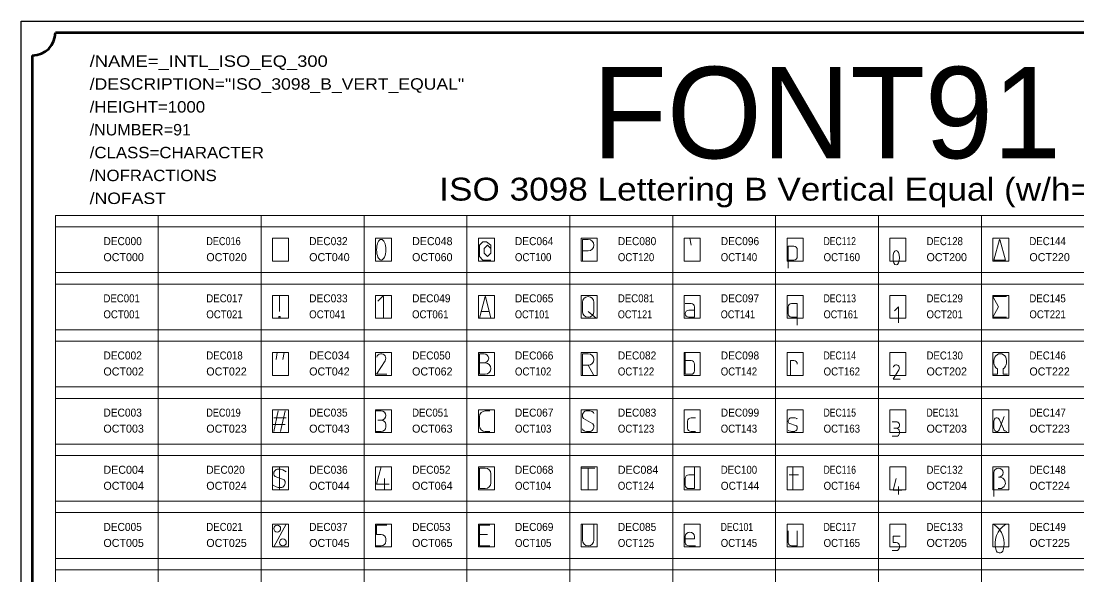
# Model space of a CAD drawing. Extents: x -200 to 7300, y -200 to 4800.
# Drawn here: x -200 to 4418, y 2378 to 4800 of the extents above; entities that cross this region are included whole.
import ezdxf
from ezdxf.enums import TextEntityAlignment as Align

# ---------------------------------------------------------------- set-up
doc = ezdxf.new("R2010")
doc.units = 0
doc.header["$LTSCALE"] = 14
for name, color, linetype, lineweight in [('1', 7, 'Continuous', 13), ('5', 7, 'Continuous', 40), ('6', 7, 'Continuous', 13), ('63', 7, 'Continuous', 13)]:
    doc.layers.add(name, color=color, linetype=linetype, lineweight=lineweight)
doc.layers.add('10', color=7, linetype='Continuous')
doc.layers.add('11', color=7, linetype='Continuous')

msp = doc.modelspace()

# ---------------------------------------------------------------- linework, layer by layer
at = {"layer": '1'}
for p, q in [((2730, 3820), (2725, 3850)), ((2280, 3795), (2255, 3795)), ((3195, 3800), (3195, 3770)), ((3180, 3755), (3155, 3755)), ((930, 3530), (930, 3600)), ((2255, 3570), (2255, 3530)), ((2305, 3570), (2305, 3530)), ((2705, 3565), (2730, 3565)), ((1813, 3530), (1848, 3530)), ((2315, 3500), (2280, 3530)), ((2720, 3535), (2745, 3535)), ((3155, 3550), (3155, 3520)), ((3170, 3505), (3195, 3505)), ((915, 3320), (920, 3350)), ((950, 3350), (945, 3320)), ((1830, 3305), (1805, 3305)), ((2280, 3295), (2255, 3295)), ((2305, 3250), (2280, 3295)), ((2730, 3315), (2705, 3315)), ((2745, 3270), (2745, 3300)), ((4055, 3315), (4055, 3305)), ((4110, 3315), (4110, 3305)), ((905, 3005), (925, 3095)), ((935, 3005), (955, 3095)), ((1375, 3095), (1350, 3095)), ((1850, 3095), (1830, 3095)), ((906, 3065), (960, 3065)), ((1375, 3055), (1360, 3055)), ((1805, 3070), (1805, 3030)), ((2715, 3050), (2715, 3020)), ((2750, 3065), (2730, 3065)), ((4055, 3050), (4055, 3020)), ((4097, 3016), (4078.8, 3055.9)), ((4100, 3070), (4079.6, 3016.6)), ((901, 3035), (955, 3035)), ((1375, 3005), (1350, 3005)), ((1395, 3035), (1395, 3025)), ((1830, 3005), (1850, 3005)), ((2730, 3005), (2750, 3005)), ((3158, 3041), (3192, 3029)), ((3628, 3047), (3610, 3047)), ((3628, 3019), (3617, 3019)), ((3642, 3005), (3642, 2998)), ((3628, 2984), (3610, 2984)), ((930, 2850), (930, 2750)), ((1855, 2820), (1855, 2780)), ((2250, 2845), (2310, 2845)), ((2280, 2845), (2280, 2750)), ((3175, 2850), (3175, 2750)), ((4055, 2720), (4055, 2825)), ((1390, 2750), (1390, 2800)), ((2705, 2770), (2705, 2800)), ((2720, 2815), (2745, 2815)), ((3160, 2815), (3200, 2815)), ((4075, 2805), (4080, 2805)), ((3638, 2730), (3638, 2765)), ((905, 2500), (960, 2600)), ((2255, 2600), (2255, 2530)), ((2305, 2600), (2305, 2530)), ((1840, 2555), (1805, 2555)), ((2705, 2520), (2705, 2545)), ((3155, 2570), (3155, 2520)), ((1350, 2505), (1375, 2505)), ((1395, 2535), (1395, 2525)), ((2750, 2505), (2720, 2505)), ((3642, 2505), (3642, 2498)), ((3610, 2484), (3628, 2484))]:
    msp.add_line(p, q, dxfattribs=at)
for points in [[(1855, 3755), (1820, 3755), (1805, 3770), (1805, 3820), (1820, 3835), (1835, 3835), (1855, 3820), (1855, 3785), (1840, 3770), (1825, 3785), (1825, 3805), (1840, 3820), (1855, 3805)], [(2280, 3845), (2255, 3845), (2255, 3750)], [(3155, 3720), (3155, 3815), (3180, 3815)], [(1385, 3500), (1385, 3595), (1380, 3595), (1360, 3575)], [(1805, 3500), (1829, 3595), (1831, 3595), (1855, 3500)], [(3195, 3470), (3195, 3565), (3170, 3565)], [(4110, 3595), (4050, 3595), (4075, 3550), (4050, 3505), (4110, 3505)], [(2745, 3550), (2745, 3505), (2720, 3505)], [(3638, 3480), (3638, 3550), (3620, 3533)], [(1825, 3345), (1805, 3345), (1805, 3255), (1830, 3255)], [(2280, 3345), (2255, 3345), (2255, 3250)], [(2705, 3350), (2705, 3255), (2730, 3255)], [(1400, 3255), (1355, 3255), (1391.8, 3314.1)], [(3180, 3315), (3165, 3315), (3165, 3250)], [(4050, 3255), (4070, 3255), (4070, 3279)], [(4115, 3255), (4095, 3255), (4095, 3279)], [(3645, 3234), (3614, 3234), (3639.3, 3274.9)], [(2305, 3083), (2303, 3088), (2298, 3092), (2294, 3094), (2287, 3095), (2270, 3095), (2266, 3094), (2262, 3091), (2258, 3085), (2256, 3081), (2255, 3077), (2255, 3069), (2260, 3062), (2300, 3038), (2305, 3031), (2305, 3023), (2304, 3019), (2302, 3015), (2298, 3009), (2294, 3006), (2290, 3005), (2273, 3005), (2266, 3006), (2262, 3008), (2257, 3012), (2255, 3017)], [(960, 2828), (945, 2837), (935, 2840), (920, 2840), (916, 2839), (912, 2836), (908.1, 2832), (905, 2827), (905, 2819), (906.8, 2812.7), (910.5, 2807.4), (950, 2793), (955, 2786), (955, 2778), (954, 2774), (952, 2770), (948, 2764), (944, 2761), (940, 2760), (925, 2760), (915, 2763), (900, 2772)], [(1410, 2775), (1355, 2775), (1375, 2850)], [(1830, 2845), (1805, 2845), (1805, 2755), (1830, 2755)], [(2745, 2850), (2745, 2755), (2720, 2755)], [(3652, 2748), (3614, 2748), (3628, 2800)], [(1400, 2595), (1355, 2595), (1355, 2555), (1375, 2555)], [(1850, 2595), (1805, 2595), (1805, 2505), (1850, 2505)], [(2705, 2535), (2745, 2535), (2745, 2545)], [(3170, 2505), (3195, 2505), (3195, 2570)], [(3645, 2547), (3614, 2547), (3614, 2519), (3628, 2519)]]:
    msp.add_lwpolyline(points, dxfattribs=at)
for points in [[(4055, 3755), (4105, 3755), (4081, 3845), (4079, 3845)], [(927, 3502), (933, 3502), (933, 3508), (927, 3508)]]:
    msp.add_lwpolyline(points, close=True, dxfattribs=at)
for centre in [(920, 2580), (945, 2520)]:
    msp.add_circle(centre, 15, dxfattribs=at)
for centre, radius, start, end in [((2280, 3820), 25, 270, 90), ((3180, 3800), 15, 0, 90), ((3180, 3770), 15, 270, 0), ((2280, 3570), 25, 0, 180), ((2730, 3550), 15, 0, 90), ((3170, 3550), 15, 90, 180), ((2280, 3530), 25, 180, 360), ((2720, 3520), 15, 90, 270), ((3170, 3520), 15, 180, 270), ((1375, 3325), 20, 327.0948, 165.9638), ((1825, 3325), 20, 270, 90), ((2280, 3320), 25, 270, 90), ((1830, 3280), 25, 270, 90), ((2730, 3300), 15, 0, 90), ((3180, 3300), 15, 0, 90), ((3627.5, 3282.5), 14, 327.0948, 165.9638), ((4085, 3305), 30, 180, 240), ((4080, 3305), 30, 300, 360), ((2730, 3270), 15, 270, 0), ((1375, 3075), 20, 270, 90), ((1830, 3070), 25, 90, 180), ((1375, 3035), 20, 0, 90), ((2730, 3050), 15, 90, 180), ((3170, 3050), 15, 105.9454, 216.8699), ((1375, 3025), 20, 270, 360), ((1830, 3030), 25, 180, 270), ((2730, 3020), 15, 180, 270), ((3180, 3020), 15, 287.9003, 36.8699), ((3628, 3033), 14, 265.8439, 90.0653), ((3628, 3005), 14, 0, 90), ((4111.2, 3020), 15, 196.6992, 270), ((3628, 2998), 14, 270, 360), ((1830, 2820), 25, 0, 90), ((4075, 2825), 20, 270, 180), ((1830, 2780), 25, 270, 0), ((2720, 2800), 15, 90, 180), ((4080, 2780), 25, 255.9638, 90), ((2720, 2770), 15, 180, 270), ((4000, 2515), 100, 340.6557, 58.2117), ((4160, 2515), 100, 121.7883, 197.354), ((1375, 2535), 20, 0, 90), ((2725, 2545), 20, 0, 180), ((1375, 2525), 20, 270, 0), ((2280, 2530), 25, 180, 360), ((2720, 2520), 15, 180, 270), ((3170, 2520), 15, 180, 270), ((3628, 2505), 14, 0, 90), ((3628, 2498), 14, 270, 360), ((4080.2, 2490.2), 16.4, 197.5688, 329.793)]:
    msp.add_arc(centre, radius, start, end, dxfattribs=at)
for centre, major_axis in [((1375, 3800), (0, -45)), ((3627.5, 3765), (0, -31.5))]:
    msp.add_ellipse(centre, major_axis=major_axis, ratio=0.444444, dxfattribs=at)
for centre, major_axis, ratio, start_param, end_param in [((4082.5, 3315), (0, 30), 0.916667, 4.712389, 7.853982), ((3175, 3060), (-20, 0), 0.25, 3.141593, 5.175477), ((4067.4, 3050), (0, 15), 0.826312, 5.117281, 7.853982), ((3175, 3010), (-20, 0), 0.25, 6.283185, 8.366111), ((4067.5, 3020), (0, 15), 0.831124, 1.570796, 4.483126)]:
    msp.add_ellipse(centre, major_axis=major_axis, ratio=ratio, start_param=start_param, end_param=end_param, dxfattribs=at)
at = {"layer": '5', "lineweight": 53}
for p, q in [((-50, 4750), (7150, 4750)), ((-150, -50), (-150, 4650))]:
    msp.add_line(p, q, dxfattribs=at)
at = {"layer": '5', "lineweight": 25}
msp.add_lwpolyline([(-200, -200), (-200, 4800), (7300, 4800), (7300, -200)], close=True, dxfattribs=at)
at = {"layer": '5', "lineweight": 53}
msp.add_arc((-150, 4750), 100, 270, 0, dxfattribs=at)
at = {"layer": '6'}
for p, q in [((-50, 3950), (7150, 3950)), ((-50, 3950), (-50, -50)), ((400, 3950), (400, -50)), ((850, 3950), (850, -50)), ((1300, 3950), (1300, -50)), ((1750, 3950), (1750, -50)), ((2200, 3950), (2200, -50)), ((2650, 3950), (2650, -50)), ((3100, 3950), (3100, -50)), ((3550, 3950), (3550, -50)), ((4000, 3950), (4000, -50)), ((-50, 3900), (7150, 3900)), ((-50, 3700), (7150, 3700)), ((-50, 3650), (7150, 3650)), ((-50, 3450), (7150, 3450)), ((-50, 3400), (7150, 3400)), ((-50, 3200), (7150, 3200)), ((-50, 3150), (7150, 3150)), ((-50, 2950), (7150, 2950)), ((-50, 2900), (7150, 2900)), ((-50, 2700), (7150, 2700)), ((-50, 2650), (7150, 2650)), ((-50, 2450), (7150, 2450)), ((-50, 2400), (7150, 2400))]:
    msp.add_line(p, q, dxfattribs=at)
at = {"layer": '63'}
for points in [[(900, 3750), (970, 3750), (970, 3850), (900, 3850)], [(1350, 3750), (1420, 3750), (1420, 3850), (1350, 3850)], [(1800, 3750), (1870, 3750), (1870, 3850), (1800, 3850)], [(2250, 3750), (2320, 3750), (2320, 3850), (2250, 3850)], [(2700, 3750), (2770, 3750), (2770, 3850), (2700, 3850)], [(3150, 3750), (3220, 3750), (3220, 3850), (3150, 3850)], [(3600, 3750), (3670, 3750), (3670, 3850), (3600, 3850)], [(4050, 3750), (4120, 3750), (4120, 3850), (4050, 3850)], [(900, 3500), (970, 3500), (970, 3600), (900, 3600)], [(1350, 3500), (1420, 3500), (1420, 3600), (1350, 3600)], [(1800, 3500), (1870, 3500), (1870, 3600), (1800, 3600)], [(2250, 3500), (2320, 3500), (2320, 3600), (2250, 3600)], [(2700, 3500), (2770, 3500), (2770, 3600), (2700, 3600)], [(3150, 3500), (3220, 3500), (3220, 3600), (3150, 3600)], [(3600, 3500), (3670, 3500), (3670, 3600), (3600, 3600)], [(4050, 3500), (4120, 3500), (4120, 3600), (4050, 3600)], [(900, 3250), (970, 3250), (970, 3350), (900, 3350)], [(1350, 3250), (1420, 3250), (1420, 3350), (1350, 3350)], [(1800, 3250), (1870, 3250), (1870, 3350), (1800, 3350)], [(2250, 3250), (2320, 3250), (2320, 3350), (2250, 3350)], [(2700, 3250), (2770, 3250), (2770, 3350), (2700, 3350)], [(3150, 3250), (3220, 3250), (3220, 3350), (3150, 3350)], [(3600, 3250), (3670, 3250), (3670, 3350), (3600, 3350)], [(4050, 3250), (4120, 3250), (4120, 3350), (4050, 3350)], [(900, 3000), (970, 3000), (970, 3100), (900, 3100)], [(1350, 3000), (1420, 3000), (1420, 3100), (1350, 3100)], [(1800, 3000), (1870, 3000), (1870, 3100), (1800, 3100)], [(2250, 3000), (2320, 3000), (2320, 3100), (2250, 3100)], [(2700, 3000), (2770, 3000), (2770, 3100), (2700, 3100)], [(3150, 3000), (3220, 3000), (3220, 3100), (3150, 3100)], [(3600, 3000), (3670, 3000), (3670, 3100), (3600, 3100)], [(4050, 3000), (4120, 3000), (4120, 3100), (4050, 3100)], [(900, 2750), (970, 2750), (970, 2850), (900, 2850)], [(1350, 2750), (1420, 2750), (1420, 2850), (1350, 2850)], [(1800, 2750), (1870, 2750), (1870, 2850), (1800, 2850)], [(2250, 2750), (2320, 2750), (2320, 2850), (2250, 2850)], [(2700, 2750), (2770, 2750), (2770, 2850), (2700, 2850)], [(3150, 2750), (3220, 2750), (3220, 2850), (3150, 2850)], [(3600, 2750), (3670, 2750), (3670, 2850), (3600, 2850)], [(4050, 2750), (4120, 2750), (4120, 2850), (4050, 2850)], [(900, 2500), (970, 2500), (970, 2600), (900, 2600)], [(1350, 2500), (1420, 2500), (1420, 2600), (1350, 2600)], [(1800, 2500), (1870, 2500), (1870, 2600), (1800, 2600)], [(2250, 2500), (2320, 2500), (2320, 2600), (2250, 2600)], [(2700, 2500), (2770, 2500), (2770, 2600), (2700, 2600)], [(3150, 2500), (3220, 2500), (3220, 2600), (3150, 2600)], [(3600, 2500), (3670, 2500), (3670, 2600), (3600, 2600)], [(4050, 2500), (4120, 2500), (4120, 2600), (4050, 2600)]]:
    msp.add_lwpolyline(points, close=True, dxfattribs=at)

# ---------------------------------------------------------------- texts
at = {"layer": '10'}
for s, width, p in [('DEC000', 0.95, (160, 3820)), ('DEC016', 0.85, (610, 3820)), ('DEC032', 0.95, (1060, 3820)), ('DEC064', 0.95, (1960, 3820)), ('DEC080', 0.95, (2410, 3820)), ('DEC096', 0.95, (2860, 3820)), ('DEC112', 0.8, (3310, 3820)), ('DEC128', 0.9, (3760, 3820)), ('DEC144', 0.9, (4210, 3820)), ('DEC001', 0.9, (160, 3570)), ('DEC017', 0.9, (610, 3570)), ('DEC033', 0.95, (1060, 3570)), ('DEC049', 0.95, (1510, 3570)), ('DEC065', 0.95, (1960, 3570)), ('DEC081', 0.9, (2410, 3570)), ('DEC097', 0.95, (2860, 3570)), ('DEC113', 0.8, (3310, 3570)), ('DEC129', 0.9, (3760, 3570)), ('DEC145', 0.9, (4210, 3570)), ('DEC002', 0.95, (160, 3320)), ('DEC018', 0.9, (610, 3320)), ('DEC050', 0.95, (1510, 3320)), ('DEC066', 0.95, (1960, 3320)), ('DEC082', 0.95, (2410, 3320)), ('DEC098', 0.95, (2860, 3320)), ('DEC114', 0.8, (3310, 3320)), ('DEC130', 0.9, (3760, 3320)), ('DEC146', 0.9, (4210, 3320)), ('DEC003', 0.95, (160, 3070)), ('DEC019', 0.85, (610, 3070)), ('DEC035', 0.95, (1060, 3070)), ('DEC051', 0.9, (1510, 3070)), ('DEC067', 0.95, (1960, 3070)), ('DEC083', 0.95, (2410, 3070)), ('DEC099', 0.95, (2860, 3070)), ('DEC115', 0.8, (3310, 3070)), ('DEC131', 0.8, (3760, 3070)), ('DEC147', 0.9, (4210, 3070)), ('DEC020', 0.95, (610, 2820)), ('DEC036', 0.95, (1060, 2820)), ('DEC052', 0.95, (1510, 2820)), ('DEC068', 0.95, (1960, 2820)), ('DEC100', 0.9, (2860, 2820)), ('DEC116', 0.8, (3310, 2820)), ('DEC132', 0.9, (3760, 2820)), ('DEC148', 0.9, (4210, 2820)), ('DEC005', 0.95, (160, 2570)), ('DEC021', 0.9, (610, 2570)), ('DEC037', 0.95, (1060, 2570)), ('DEC053', 0.95, (1510, 2570)), ('DEC069', 0.95, (1960, 2570)), ('DEC085', 0.95, (2410, 2570)), ('DEC101', 0.8, (2860, 2570)), ('DEC117', 0.8, (3310, 2570)), ('DEC133', 0.9, (3760, 2570)), ('DEC149', 0.9, (4210, 2570))]:
    msp.add_text(s, height=35, dxfattribs=dict(at, width=width)).set_placement(p)
for s, p in [('DEC048', (1510, 3820)), ('DEC034', (1060, 3320)), ('DEC004', (160, 2820)), ('DEC084', (2410, 2820))]:
    msp.add_text(s, height=35, dxfattribs=at).set_placement(p)
at = {"layer": '11'}
for s, p in [('OCT000', (160, 3750)), ('OCT020', (610, 3750)), ('OCT040', (1060, 3750)), ('OCT060', (1510, 3750)), ('OCT200', (3760, 3750)), ('OCT220', (4210, 3750)), ('OCT002', (160, 3250)), ('OCT022', (610, 3250)), ('OCT042', (1060, 3250)), ('OCT062', (1510, 3250)), ('OCT202', (3760, 3250)), ('OCT222', (4210, 3250)), ('OCT003', (160, 3000)), ('OCT023', (610, 3000)), ('OCT043', (1060, 3000)), ('OCT063', (1510, 3000)), ('OCT203', (3760, 3000)), ('OCT223', (4210, 3000)), ('OCT004', (160, 2750)), ('OCT024', (610, 2750)), ('OCT044', (1060, 2750)), ('OCT064', (1510, 2750)), ('OCT204', (3760, 2750)), ('OCT224', (4210, 2750)), ('OCT005', (160, 2500)), ('OCT025', (610, 2500)), ('OCT045', (1060, 2500)), ('OCT065', (1510, 2500)), ('OCT205', (3760, 2500)), ('OCT225', (4210, 2500))]:
    msp.add_text(s, height=35, dxfattribs=at).set_placement(p)
for s, width, p in [('OCT100', 0.9, (1960, 3750)), ('OCT120', 0.9, (2410, 3750)), ('OCT140', 0.9, (2860, 3750)), ('OCT160', 0.9, (3310, 3750)), ('OCT001', 0.9, (160, 3500)), ('OCT021', 0.9, (610, 3500)), ('OCT041', 0.9, (1060, 3500)), ('OCT061', 0.9, (1510, 3500)), ('OCT101', 0.85, (1960, 3500)), ('OCT121', 0.85, (2410, 3500)), ('OCT141', 0.85, (2860, 3500)), ('OCT161', 0.85, (3310, 3500)), ('OCT201', 0.9, (3760, 3500)), ('OCT221', 0.9, (4210, 3500)), ('OCT102', 0.9, (1960, 3250)), ('OCT122', 0.9, (2410, 3250)), ('OCT142', 0.9, (2860, 3250)), ('OCT162', 0.9, (3310, 3250)), ('OCT103', 0.9, (1960, 3000)), ('OCT123', 0.9, (2410, 3000)), ('OCT143', 0.9, (2860, 3000)), ('OCT163', 0.9, (3310, 3000)), ('OCT104', 0.9, (1960, 2750)), ('OCT124', 0.9, (2410, 2750)), ('OCT144', 0.95, (2860, 2750)), ('OCT164', 0.9, (3310, 2750)), ('OCT105', 0.9, (1960, 2500)), ('OCT125', 0.9, (2410, 2500)), ('OCT145', 0.9, (2860, 2500)), ('OCT165', 0.9, (3310, 2500))]:
    msp.add_text(s, height=35, dxfattribs=dict(at, width=width)).set_placement(p)
at = {"layer": '5'}
msp.add_text('FONT91', height=400, dxfattribs=at).set_placement((3323, 4200), align=Align.CENTER)
at = {"layer": '5', "width": 1.15}
msp.add_text('ISO 3098 Lettering B Vertical Equal (w/h=7/10)', height=100, dxfattribs=at).set_placement((3229.5, 4015), align=Align.CENTER)
at = {"layer": '63'}
for s, width, p in [('/NAME=_INTL_ISO_EQ_300', 1.2, (100, 4600)), ('/DESCRIPTION="ISO_3098_B_VERT_EQUAL"', 1.15, (100, 4500)), ('/HEIGHT=1000', 1.1, (100, 4400)), ('/NUMBER=91', 1.05, (100, 4300)), ('/CLASS=CHARACTER', 1.1, (100, 4200)), ('/NOFRACTIONS', 1.1, (100, 4100)), ('/NOFAST', 1.15, (100, 4000))]:
    msp.add_text(s, height=50, dxfattribs=dict(at, width=width)).set_placement(p)

doc.saveas('drawing.dxf')
